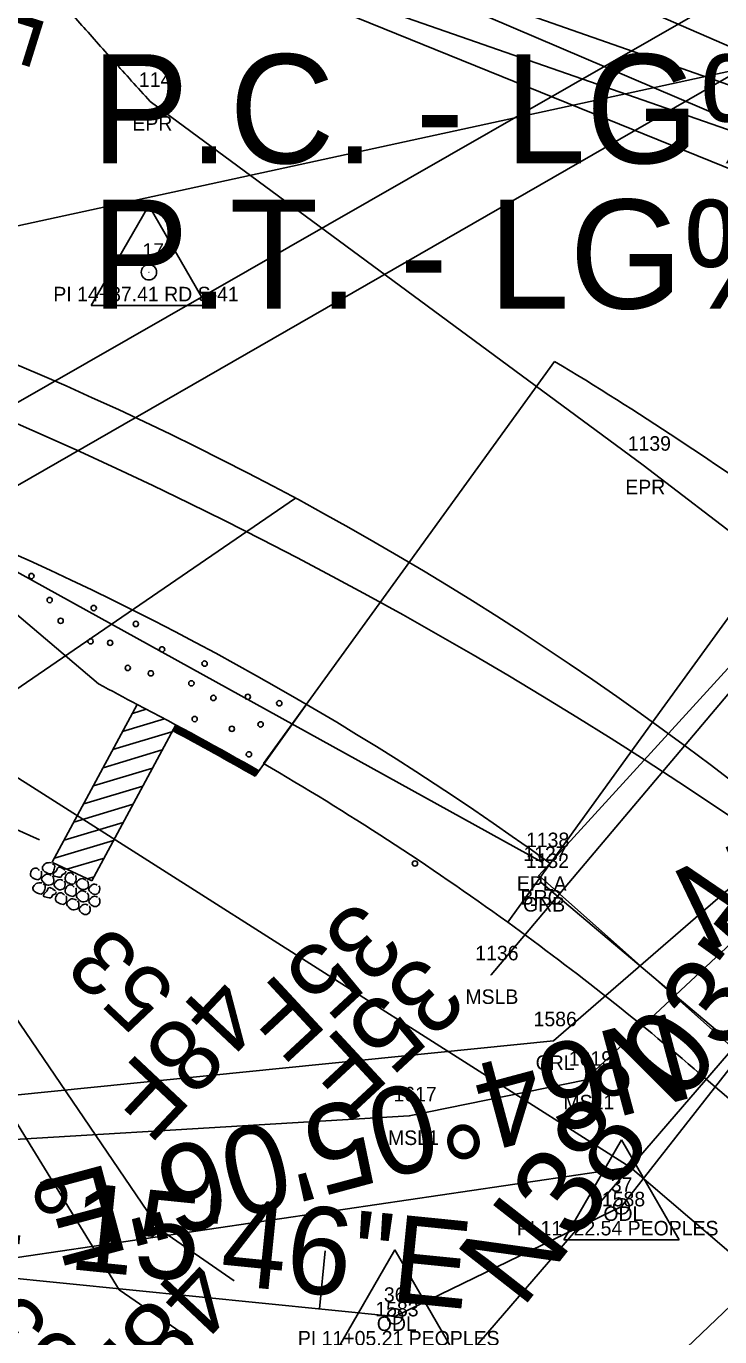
# Model space of a CAD drawing. Extents: x 1812113 to 1819860, y 1177395 to 1181185.
# Drawn here: x 1813697.5 to 1813745.2, y 1178675.3 to 1178765.4 of the extents above; entities that cross this region are included whole.
import ezdxf

# ---------------------------------------------------------------- set-up
doc = ezdxf.new("R2010")
doc.units = 0
for name, color, linetype in [('RD_EX_Bridge', 7, 'Continuous'), ('RD_EX_Bridge_txCode', 7, 'Continuous'), ('RD_EX_DV_Prop', 7, 'Continuous'), ('RD_EX_GuardRail', 7, 'Continuous'), ('RD_EX_GuardRail_txCode', 7, 'Continuous'), ('RD_EX_H2O', 7, 'Continuous'), ('RD_EX_H2O_txCode', 7, 'Continuous'), ('RD_EX_Misc', 7, 'Continuous'), ('RD_EX_Misc_txCode', 7, 'Continuous'), ('RD_EX_Road', 7, 'Continuous'), ('RD_EX_Road_txCode', 7, 'Continuous'), ('RD_EX_RW', 7, 'Continuous'), ('RD_EX_UT', 7, 'Continuous'), ('RD_HC_CL', 7, 'Continuous'), ('RD_HC_Data', 7, 'Continuous'), ('RD_HC_Data_Tic', 7, 'Continuous'), ('RD_HC_TX_StaOther', 7, 'Continuous'), ('RD_HC_txCode', 7, 'Continuous'), ('RD_PD_ALT1_TnTmp', 7, 'Continuous'), ('RD_PD_ALT1_TrvlWay', 7, 'Continuous'), ('RD_PD_ALT3_LnLine', 7, 'Continuous'), ('RD_PD_ALT4_LnLine', 7, 'Continuous'), ('RD_PD_Bridge', 7, 'Continuous'), ('RD_PD_CstnLmt', 7, 'Continuous'), ('RD_PD_PatLn1', 7, 'Continuous'), ('RD_PD_RW', 7, 'Continuous'), ('RD_SMD_Locator', 7, 'Continuous')]:
    doc.layers.add(name, color=color, linetype=linetype)

msp = doc.modelspace()

# ---------------------------------------------------------------- linework, layer by layer
at = {"layer": 'RD_EX_Bridge'}
msp.add_lwpolyline([(1813761.421, 1178681.528), (1813780.287, 1178703.501), (1813751.527, 1178727.564), (1813732.759, 1178706.999), (1813761.421, 1178681.528)], dxfattribs=at)
at = {"layer": 'RD_EX_DV_Prop'}
msp.add_line((1813739.051, 1178686.932), (1813534.091, 1178656.724), dxfattribs=at)
at = {"layer": 'RD_EX_GuardRail'}
msp.add_line((1813762.326, 1178681.712), (1813732.928, 1178706.518), dxfattribs=at)
at = {"layer": 'RD_EX_H2O'}
msp.add_lwpolyline([(1813499.617, 1178706.366), (1813533.114, 1178716.309), (1813566.868, 1178706.45), (1813581.023, 1178703.792), (1813602.73, 1178697.665), (1813630.178, 1178688.942), (1813658.74, 1178690.222), (1813683.523, 1178690.556), (1813733.773, 1178695.63), (1813767.86, 1178725.164), (1813778.937, 1178729.947)], dxfattribs=at)
at = {"layer": 'RD_EX_Misc'}
msp.add_line((1813755.419, 1178730.93), (1813729.479, 1178700.165), dxfattribs=at)
for points in [[(1813405.705, 1178572.738), (1813779.174, 1178786.696), (1813799.347, 1179222.212)], [(1813408.465, 1178567.925), (1813786.329, 1178785.294), (1813804.76, 1179221.827)], [(1813573.261, 1178698.609), (1813581.176, 1178685.417), (1813588.271, 1178683.03), (1813621.867, 1178683.405), (1813652.093, 1178681.47), (1813685.623, 1178688.184), (1813723.849, 1178690.459), (1813735.911, 1178692.91), (1813768.219, 1178723.128), (1813784.539, 1178734.4), (1813800.789, 1178738.457), (1813839.236, 1178736.87), (1813863.895, 1178734.392), (1813884.494, 1178732.558), (1813903.275, 1178733.231)], [(1813591.145, 1178668.772), (1813628.984, 1178667.844), (1813655.761, 1178668.83), (1813686.954, 1178670.41), (1813726.51, 1178669.36), (1813738.941, 1178670.711), (1813788.676, 1178718.193), (1813806.253, 1178725.658), (1813819.179, 1178726.191), (1813847.084, 1178721.307), (1813860.38, 1178717.648), (1813871.967, 1178724.247), (1813883.921, 1178723.481), (1813902.674, 1178722.415)]]:
    msp.add_lwpolyline(points, dxfattribs=at)
at = {"layer": 'RD_EX_Road'}
for p, q in [((1813739.938, 1178735.225), (1813706.04, 1178760.253)), ((1813750.48, 1178727.166), (1813739.938, 1178735.225))]:
    msp.add_line(p, q, dxfattribs=at)
msp.add_lwpolyline([(1813732.944, 1178707.952), (1813689.881, 1178731.75), (1813641.709, 1178744.362), (1813593.37, 1178752.087), (1813544.486, 1178758.767), (1813495.448, 1178766.292), (1813446.797, 1178774.656), (1813426.541, 1178777.947), (1813403.207, 1178782.553), (1813398.647, 1178783.844), (1813350.676, 1178796.087), (1813343.234, 1178797.919), (1813318.695, 1178804.226), (1813303.263, 1178808.847), (1813256.804, 1178823.167), (1813209.806, 1178838.912), (1813163.269, 1178855.568)], dxfattribs=at)
msp.add_open_spline([(1813706.04, 1178760.253), (1813693.675, 1178773.776), (1813687.152, 1178785.679), (1813683.913, 1178796.533)], degree=2, dxfattribs=at)
at = {"layer": 'RD_EX_RW'}
for p, q in [((1813768.43, 1178754.211), (1813729.798, 1178771.044)), ((1813686.842, 1178720.142), (1813739.051, 1178686.932)), ((1813782.499, 1178649.754), (1813739.051, 1178686.932))]:
    msp.add_line(p, q, dxfattribs=at)
at = {"layer": 'RD_EX_UT'}
msp.add_lwpolyline([(1813817.449, 1178777.901), (1813490.203, 1178706.765), (1813294.329, 1178669.417)], dxfattribs=at)
at = {"layer": 'RD_HC_CL'}
for p, q in [((1813738.448, 1178684.24), (1813755.38, 1178705.863)), ((1813722.865, 1178676.669), (1813738.448, 1178684.24)), ((1813688.258, 1178680.146), (1813722.865, 1178676.669))]:
    msp.add_line(p, q, dxfattribs=at)
msp.add_arc((1813611.441, 1178538.999), 220.368, 49.21843, 82.2191, dxfattribs=at)
at = {"layer": 'RD_HC_Data'}
for p, q in [((1813701.981, 1178746.207), (1813705.953, 1178753.087)), ((1813705.953, 1178753.087), (1813709.922, 1178746.207)), ((1813701.981, 1178746.207), (1813709.922, 1178746.207)), ((1813755.38, 1178705.862), (1813645.021, 1178577.927)), ((1813734.477, 1178681.947), (1813738.449, 1178688.827)), ((1813738.449, 1178688.827), (1813742.418, 1178681.947)), ((1813718.894, 1178674.376), (1813722.866, 1178681.256)), ((1813722.866, 1178681.256), (1813726.835, 1178674.376)), ((1813734.477, 1178681.947), (1813742.418, 1178681.947))]:
    msp.add_line(p, q, dxfattribs=at)
for centre in [(1813705.952, 1178748.5), (1813738.448, 1178684.24), (1813722.865, 1178676.669)]:
    msp.add_circle(centre, 0.529, dxfattribs=at)
at = {"layer": 'RD_HC_Data_Tic'}
msp.add_line((1813717.679, 1178677.19), (1813718.079, 1178681.17), dxfattribs=at)
at = {"layer": 'RD_PD_ALT1_TrvlWay'}
for p, q in [((1813687.275, 1178733.077), (1813702.495, 1178720.178)), ((1813705.138, 1178718.758), (1813699.309, 1178707.912)), ((1813705.758, 1178718.437), (1813704.813, 1178718.153)), ((1813716.815, 1178718.818), (1813713.249, 1178713.831)), ((1813707.795, 1178717.366), (1813702.025, 1178706.627)), ((1813707.025, 1178717.774), (1813704.143, 1178716.907)), ((1813707.537, 1178716.884), (1813703.474, 1178715.662)), ((1813706.867, 1178715.638), (1813702.805, 1178714.416)), ((1813706.198, 1178714.393), (1813702.135, 1178713.17)), ((1813705.528, 1178713.147), (1813701.466, 1178711.924)), ((1813704.859, 1178711.901), (1813700.796, 1178710.679)), ((1813704.189, 1178710.655), (1813700.127, 1178709.433)), ((1813703.52, 1178709.41), (1813699.457, 1178708.187)), ((1813702.794, 1178708.175), (1813700.307, 1178707.442)), ((1813699.311, 1178707.905), (1813702.025, 1178706.627)), ((1813702.181, 1178706.918), (1813701.713, 1178706.777))]:
    msp.add_line(p, q, dxfattribs=at)
for centre in [(1813697.874, 1178727.6), (1813699.127, 1178725.95), (1813702.159, 1178725.397), (1813699.882, 1178724.521), (1813705.052, 1178724.309), (1813701.937, 1178723.11), (1813703.283, 1178723.009), (1813706.856, 1178722.555), (1813709.782, 1178721.581), (1813704.498, 1178721.28), (1813706.084, 1178720.908), (1813708.87, 1178720.222), (1813710.384, 1178719.217), (1813712.75, 1178719.291), (1813714.916, 1178718.849), (1813709.098, 1178717.763), (1813711.654, 1178717.09), (1813713.63, 1178717.395), (1813712.83, 1178715.336), (1813724.243, 1178707.825)]:
    msp.add_circle(centre, 0.182, dxfattribs=at)
for centre, radius, start, end in [((1813611.441, 1178538.999), 208.368, 54.12303, 82.2191), ((1813607.835, 1178540.857), 202.772, 61.32368, 62.17159), ((1813612.433, 1178538.481), 202.717, 60.09099, 62.78613), ((1813612.433, 1178538.481), 202.467, 60.09799, 61.93839), ((1813612.433, 1178538.481), 202.517, 60.09658, 61.93835), ((1813612.433, 1178538.481), 202.567, 60.09517, 61.9383), ((1813612.433, 1178538.481), 202.618, 60.09376, 61.93825), ((1813612.433, 1178538.481), 202.668, 60.09236, 61.9382), ((1813612.433, 1178538.481), 202.266, 60.10363, 61.93858), ((1813612.433, 1178538.481), 202.317, 60.10222, 61.93853), ((1813612.433, 1178538.481), 202.367, 60.10081, 61.93849), ((1813612.433, 1178538.481), 202.417, 60.0994, 61.93844)]:
    msp.add_arc(centre, radius, start, end, dxfattribs=at)
for points in [[(1813698.411, 1178707.345), (1813698.229, 1178707.5), (1813697.977, 1178707.457), (1813697.858, 1178707.303), (1813697.806, 1178707.143), (1813697.848, 1178706.937), (1813698.001, 1178706.818), (1813698.153, 1178706.747), (1813698.323, 1178706.713), (1813698.48, 1178706.802), (1813698.552, 1178706.954), (1813698.567, 1178707.132), (1813698.534, 1178707.31)], [(1813699.243, 1178707.879), (1813699.036, 1178707.883), (1813698.849, 1178707.832), (1813698.721, 1178707.707), (1813698.63, 1178707.564), (1813698.721, 1178707.312), (1813698.864, 1178707.222), (1813699.016, 1178707.15), (1813699.185, 1178707.117), (1813699.343, 1178707.205), (1813699.415, 1178707.357), (1813699.467, 1178707.518), (1813699.463, 1178707.706), (1813699.329, 1178707.815)], [(1813700.188, 1178707.375), (1813700.045, 1178707.465), (1813699.902, 1178707.556), (1813699.724, 1178707.57), (1813699.633, 1178707.427), (1813699.543, 1178707.284), (1813699.414, 1178707.159), (1813699.38, 1178706.989), (1813699.56, 1178706.928), (1813699.749, 1178706.885), (1813699.927, 1178706.917), (1813699.998, 1178707.069), (1813700.166, 1178707.13), (1813700.246, 1178707.301)], [(1813698.588, 1178706.489), (1813698.382, 1178706.494), (1813698.195, 1178706.442), (1813698.067, 1178706.317), (1813697.976, 1178706.174), (1813698.066, 1178705.923), (1813698.209, 1178705.832), (1813698.361, 1178705.761), (1813698.531, 1178705.727), (1813698.689, 1178705.815), (1813698.76, 1178705.967), (1813698.813, 1178706.128), (1813698.808, 1178706.316), (1813698.674, 1178706.426)], [(1813699.24, 1178707), (1813699.072, 1178707.079), (1813698.885, 1178707.091), (1813698.737, 1178706.996), (1813698.604, 1178706.859), (1813698.583, 1178706.683), (1813698.689, 1178706.544), (1813698.826, 1178706.411), (1813698.994, 1178706.345), (1813699.166, 1178706.361), (1813699.337, 1178706.431), (1813699.411, 1178706.603), (1813699.398, 1178706.795), (1813699.305, 1178706.962)], [(1813700.022, 1178706.659), (1813699.84, 1178706.724), (1813699.674, 1178706.679), (1813699.545, 1178706.567), (1813699.435, 1178706.406), (1813699.481, 1178706.24), (1813699.62, 1178706.112), (1813699.778, 1178706.024), (1813699.945, 1178706.028), (1813700.093, 1178706.11), (1813700.176, 1178706.27), (1813700.185, 1178706.452), (1813700.129, 1178706.609)], [(1813700.793, 1178707.033), (1813700.611, 1178707.188), (1813700.358, 1178707.145), (1813700.24, 1178706.992), (1813700.187, 1178706.831), (1813700.23, 1178706.625), (1813700.383, 1178706.507), (1813700.535, 1178706.435), (1813700.704, 1178706.402), (1813700.862, 1178706.49), (1813700.934, 1178706.642), (1813700.948, 1178706.821), (1813700.916, 1178706.998)], [(1813700.803, 1178706.196), (1813700.621, 1178706.351), (1813700.369, 1178706.308), (1813700.25, 1178706.155), (1813700.198, 1178705.994), (1813700.24, 1178705.788), (1813700.393, 1178705.67), (1813700.545, 1178705.598), (1813700.715, 1178705.565), (1813700.872, 1178705.653), (1813700.944, 1178705.805), (1813700.959, 1178705.984), (1813700.926, 1178706.161)], [(1813701.622, 1178706.688), (1813701.453, 1178706.767), (1813701.267, 1178706.78), (1813701.119, 1178706.684), (1813700.985, 1178706.547), (1813700.964, 1178706.372), (1813701.071, 1178706.232), (1813701.207, 1178706.099), (1813701.376, 1178706.033), (1813701.548, 1178706.049), (1813701.719, 1178706.119), (1813701.793, 1178706.291), (1813701.78, 1178706.483), (1813701.687, 1178706.65)], [(1813702.404, 1178706.347), (1813702.221, 1178706.413), (1813702.055, 1178706.367), (1813701.927, 1178706.255), (1813701.817, 1178706.094), (1813701.862, 1178705.928), (1813702.002, 1178705.801), (1813702.16, 1178705.713), (1813702.326, 1178705.716), (1813702.475, 1178705.798), (1813702.557, 1178705.959), (1813702.567, 1178706.14), (1813702.51, 1178706.297)], [(1813699.521, 1178705.957), (1813699.378, 1178706.048), (1813699.235, 1178706.138), (1813699.056, 1178706.153), (1813698.966, 1178706.01), (1813698.875, 1178705.867), (1813698.747, 1178705.742), (1813698.713, 1178705.572), (1813698.893, 1178705.51), (1813699.082, 1178705.468), (1813699.259, 1178705.5), (1813699.331, 1178705.652), (1813699.499, 1178705.713), (1813699.579, 1178705.884)], [(1813700.139, 1178705.643), (1813699.957, 1178705.799), (1813699.704, 1178705.755), (1813699.586, 1178705.602), (1813699.533, 1178705.441), (1813699.575, 1178705.235), (1813699.728, 1178705.117), (1813699.88, 1178705.045), (1813700.05, 1178705.012), (1813700.208, 1178705.1), (1813700.279, 1178705.252), (1813700.294, 1178705.431), (1813700.262, 1178705.609)], [(1813701.633, 1178705.851), (1813701.464, 1178705.93), (1813701.277, 1178705.943), (1813701.129, 1178705.847), (1813700.996, 1178705.71), (1813700.975, 1178705.535), (1813701.081, 1178705.395), (1813701.218, 1178705.262), (1813701.386, 1178705.196), (1813701.558, 1178705.212), (1813701.729, 1178705.283), (1813701.803, 1178705.454), (1813701.79, 1178705.646), (1813701.697, 1178705.813)], [(1813702.414, 1178705.51), (1813702.232, 1178705.576), (1813702.066, 1178705.53), (1813701.938, 1178705.418), (1813701.827, 1178705.257), (1813701.873, 1178705.091), (1813702.012, 1178704.964), (1813702.17, 1178704.876), (1813702.337, 1178704.88), (1813702.485, 1178704.961), (1813702.568, 1178705.122), (1813702.577, 1178705.303), (1813702.521, 1178705.46)], [(1813700.968, 1178705.298), (1813700.799, 1178705.378), (1813700.612, 1178705.39), (1813700.464, 1178705.295), (1813700.331, 1178705.158), (1813700.31, 1178704.982), (1813700.416, 1178704.843), (1813700.553, 1178704.709), (1813700.722, 1178704.644), (1813700.894, 1178704.659), (1813701.065, 1178704.73), (1813701.138, 1178704.901), (1813701.126, 1178705.093), (1813701.033, 1178705.261)], [(1813701.749, 1178704.958), (1813701.567, 1178705.023), (1813701.401, 1178704.977), (1813701.273, 1178704.866), (1813701.163, 1178704.704), (1813701.208, 1178704.539), (1813701.347, 1178704.411), (1813701.505, 1178704.323), (1813701.672, 1178704.327), (1813701.821, 1178704.408), (1813701.903, 1178704.569), (1813701.913, 1178704.75), (1813701.856, 1178704.907)]]:
    msp.add_spline(points, degree=3, dxfattribs=at)
at = {"layer": 'RD_PD_ALT3_LnLine'}
for p, q in [((1813756.393, 1178757.69), (1813700.676, 1178777.201)), ((1813754.735, 1178755.19), (1813699.624, 1178774.391)), ((1813679.978, 1178721.95), (1813706.67, 1178682.672)), ((1813703.908, 1178678.505), (1813678.926, 1178719.141)), ((1813706.67, 1178682.672), (1813711.822, 1178679.121)), ((1813708.91, 1178675.057), (1813703.908, 1178678.505))]:
    msp.add_line(p, q, dxfattribs=at)
at = {"layer": 'RD_PD_ALT4_LnLine'}
for p, q in [((1813754.735, 1178755.19), (1813701.027, 1178778.137)), ((1813753.078, 1178752.689), (1813699.624, 1178774.391)), ((1813554.387, 1178622.309), (1813716.04, 1178732.96)), ((1813698.43, 1178709.453), (1813678.575, 1178718.204))]:
    msp.add_line(p, q, dxfattribs=at)
at = {"layer": 'RD_PD_Bridge'}
for p, q in [((1813733.849, 1178742.37), (1813724.381, 1178729.279)), ((1813713.841, 1178714.705), (1813724.381, 1178729.279)), ((1813747.619, 1178727.281), (1813740.587, 1178717.558)), ((1813730.624, 1178703.783), (1813740.587, 1178717.558)), ((1813761.038, 1178678.531), (1813744.276, 1178692.99))]:
    msp.add_line(p, q, dxfattribs=at)
for radius, start, end in [(237.368, 54.12303, 58.95636), (203.368, 54.12303, 59.76685), (203.368, 49.21843, 54.12303)]:
    msp.add_arc((1813611.441, 1178538.999), radius, start, end, dxfattribs=at)
at = {"layer": 'RD_PD_PatLn1'}
msp.add_arc((1813574.818, 1178458.585), 305, 48.82062, 82.2191, dxfattribs=at)
at = {"layer": 'RD_PD_RW'}
msp.add_arc((1813611.441, 1178538.999), 145.368, 49.21843, 73.8831, dxfattribs=at)
at = {"layer": 'RD_SMD_Locator'}
for centre in [(1813706.04, 1178760.253), (1813705.952, 1178748.5), (1813739.938, 1178735.225), (1813732.944, 1178707.952), (1813732.759, 1178706.999), (1813732.928, 1178706.518), (1813729.479, 1178700.165), (1813733.773, 1178695.63), (1813735.911, 1178692.91), (1813723.849, 1178690.459), (1813738.448, 1178684.24), (1813738.448, 1178684.24), (1813722.865, 1178676.669), (1813722.865, 1178676.669)]:
    msp.add_circle(centre, 0.001, dxfattribs=at)

# ---------------------------------------------------------------- texts
at = {"layer": 'RD_EX_Bridge_txCode'}
for s, p in [('1127', (1813731.696, 1178707.999)), ('BRC', (1813731.507, 1178704.999))]:
    msp.add_text(s, height=1, dxfattribs=at).set_placement(p)
at = {"layer": 'RD_EX_GuardRail_txCode'}
for s, p in [('1132', (1813731.865, 1178707.518)), ('GRB', (1813731.676, 1178704.518))]:
    msp.add_text(s, height=1, dxfattribs=at).set_placement(p)
at = {"layer": 'RD_EX_H2O_txCode'}
for s, p in [('1586', (1813732.403, 1178696.63)), ('CRL', (1813732.545, 1178693.63)), ('1588', (1813737.101, 1178684.24)), ('ODL', (1813737.204, 1178683.24)), ('1583', (1813721.519, 1178676.669)), ('ODL', (1813721.621, 1178675.669))]:
    msp.add_text(s, height=1, dxfattribs=at).set_placement(p)
at = {"layer": 'RD_EX_Misc_txCode'}
for s, p in [('1136', (1813728.392, 1178701.165)), ('MSLB', (1813727.715, 1178698.165)), ('1619', (1813734.824, 1178693.91)), ('1617', (1813722.763, 1178691.459)), ('MSL1', (1813734.454, 1178690.91)), ('MSL1', (1813722.393, 1178688.459))]:
    msp.add_text(s, height=1, dxfattribs=at).set_placement(p)
at = {"layer": 'RD_EX_Road_txCode'}
for s, p in [('1141', (1813705.261, 1178761.253)), ('EPR', (1813704.812, 1178758.253)), ('1139', (1813738.875, 1178736.225)), ('EPR', (1813738.71, 1178733.225)), ('1138', (1813731.881, 1178708.952)), ('EPLA', (1813731.251, 1178705.952))]:
    msp.add_text(s, height=1, dxfattribs=at).set_placement(p)
at = {"layer": 'RD_HC_TX_StaOther'}
for s, p in [('P.C. - LG% = ', (1813702, 1178756)), ('P.T. - LG% = ', (1813702, 1178746))]:
    msp.add_text(s, height=7.5, dxfattribs=at).set_placement(p)
at = {"layer": 'RD_HC_txCode'}
for s, p in [('17', (1813705.503, 1178749.5)), ('PI 14+87.41 RD S-41', (1813699.377, 1178746.5)), ('37', (1813737.715, 1178685.24)), ('PI 11+22.54 PEOPLES', (1813731.251, 1178682.24)), ('36', (1813722.109, 1178677.669)), ('PI 11+05.21 PEOPLES', (1813716.196, 1178674.669))]:
    msp.add_text(s, height=1, dxfattribs=at).set_placement(p)
at = {"layer": 'RD_PD_ALT1_TnTmp'}
for s, rotation, p in [('N64%%d23\'45"E', 25.60422, (1813744.164, 1178701.597)), ('N38%%d03\'53"E', 51.93534, (1813731.594, 1178677.11)), ('N64%%d05\'06"E', 195.01436, (1813742.084, 1178697.618)), ('S84%%d15\'46"E', 354.26274, (1813682.941, 1178681.685))]:
    msp.add_text(s, height=6, rotation=rotation, dxfattribs=at).set_placement(p)
at = {"layer": 'RD_PD_ALT3_LnLine'}
for s, height, rotation, p in [('31F', 5, 252.63614, (1813696.32, 1178774.86)), ('53', 4.5, 136.72337, (1813707.995, 1178699.14)), ('48F', 5, 226.72337, (1813710.448, 1178700.402)), ('48F', 5, 226.72337, (1813708.703, 1178680.977)), ('53', 4.5, 136.72337, (1813701.756, 1178673.925))]:
    msp.add_text(s, height=height, rotation=rotation, dxfattribs=at).set_placement(p)
at = {"layer": 'RD_PD_CstnLmt'}
for p in [(1813720.39, 1178705.495), (1813724.668, 1178701.794)]:
    msp.add_text('35F', height=5, rotation=222.86566, dxfattribs=at).set_placement(p)

doc.saveas('drawing.dxf')
